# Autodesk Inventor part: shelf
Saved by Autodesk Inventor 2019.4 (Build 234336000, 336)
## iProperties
Created: 2020-09
Part Number: shelf
Material: Generic
Document SubType Name: Modeling
Designer: Administrator
Density: 1 g/cm^3
Appearance: Default
Title: shelf
Author: Administrator
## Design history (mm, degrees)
feature "Body1"
body "Solid1"
